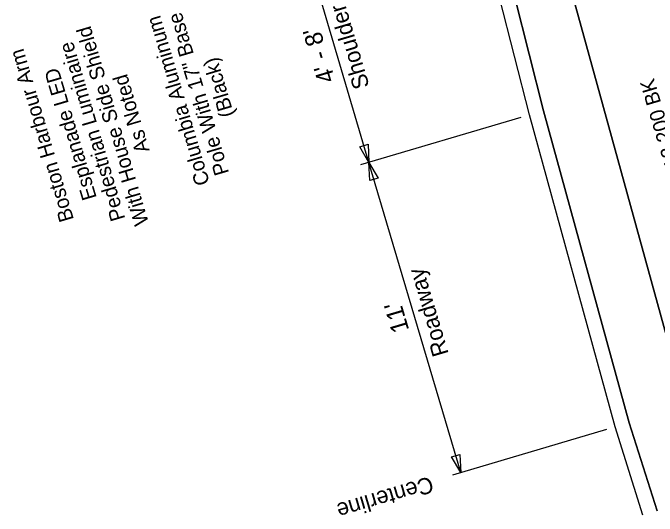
# Model space of a CAD drawing. Extents: x 1111051 to 1111820, y 617600 to 618625.
# Drawn here: x 1111518.6 to 1111693.5, y 617847.4 to 617984.1 of the extents above; entities that cross this region are included whole.
import ezdxf

# ---------------------------------------------------------------- set-up
doc = ezdxf.new("R2010")
doc.units = 0
for name, color, linetype in [('ANNOTATION', 7, 'Continuous'), ('D_Roadway_Edge_Shoulder', 7, 'Continuous'), ('D_Roadway_Edge_TW', 7, 'Continuous'), ('D_Roadway_SubGrade', 7, 'Continuous'), ('DIMENSIONS', 7, 'Continuous'), ('PATTERNING', 7, 'Continuous'), ('Prp Liting', 7, 'Continuous')]:
    doc.layers.add(name, color=color, linetype=linetype)

msp = doc.modelspace()

# ---------------------------------------------------------------- linework, layer by layer
at = {"layer": 'D_Roadway_Edge_Shoulder'}
for p, q in [((1111658.8, 617956.37), (1111643.11, 618018.35)), ((1111646.94, 618019.49), (1111662.63, 617957.5))]:
    msp.add_line(p, q, dxfattribs=at)
at = {"layer": 'D_Roadway_Edge_TW'}
for p, q in [((1111662.63, 617957.5), (1111685.88, 617872.77)), ((1111682.05, 617871.64), (1111658.8, 617956.37)), ((1111693.48, 617848.85), (1111685.88, 617872.77)), ((1111689.65, 617847.71), (1111682.05, 617871.64))]:
    msp.add_line(p, q, dxfattribs=at)
at = {"layer": 'D_Roadway_SubGrade'}
for p, q in [((1111661.03, 618023.66), (1111677.94, 617962.03)), ((1111662.63, 617957.5), (1111646.94, 618019.49)), ((1111677.94, 617962.03), (1111701.19, 617877.3)), ((1111685.88, 617872.77), (1111662.63, 617957.5)), ((1111693.48, 617848.85), (1111685.88, 617872.77))]:
    msp.add_line(p, q, dxfattribs=at)
at = {"layer": 'DIMENSIONS'}
for p, q in [((1111615.25, 617943.48), (1111597.1, 618004.77)), ((1111656.5, 617955.69), (1111612.95, 617942.8)), ((1111640.18, 617859.24), (1111615.25, 617943.48)), ((1111679.75, 617870.96), (1111637.89, 617858.56))]:
    msp.add_line(p, q, dxfattribs=at)
for points in [[(1111615.04, 617948.41), (1111615.25, 617943.48), (1111612.74, 617947.73)], [(1111615.46, 617938.54), (1111615.25, 617943.48), (1111617.76, 617939.22)], [(1111639.97, 617864.18), (1111640.18, 617859.24), (1111637.68, 617863.5)]]:
    msp.add_lwpolyline(points, close=True, dxfattribs=at)
at = {"layer": 'PATTERNING'}
for p, q in [((1111677.94, 617962.03), (1111661.03, 618023.66)), ((1111646.94, 618019.49), (1111662.63, 617957.5)), ((1111701.19, 617877.3), (1111677.94, 617962.03)), ((1111662.63, 617957.5), (1111685.88, 617872.77)), ((1111685.88, 617872.77), (1111693.48, 617848.85))]:
    msp.add_line(p, q, dxfattribs=at)

# ---------------------------------------------------------------- texts
at = {"layer": 'ANNOTATION'}
for s, rotation, p in [('Shoulder', 106.4903, (1111615.44, 617964.14)), ('Roadway', 106.4903, (1111636.93, 617891.53)), ('Centerline', 196.4903, (1111631.97, 617858.31))]:
    msp.add_text(s, height=4.425, rotation=rotation, dxfattribs=at).set_placement(p)
at = {"layer": 'Prp Liting'}
for s, height, p in [('Columbia Aluminum', 3.993, (1111572.08, 617937.86)), ('Pole With 17" Base', 3.993, (1111577.31, 617940.62)), ('With House Side Shield', 3.993, (1111555.53, 617927.01)), ("4' - 8'", 4.792, (1111606.13, 617965.84)), ('Pedestrian Luminaire', 3.993, (1111549.13, 617928.21)), ('Boston Harbour Arm', 3.993, (1111535.19, 617927.99)), ('(Black)', 3.993, (1111578.69, 617956.37)), ('Esplanade LED', 3.993, (1111541.4, 617933.89)), ('As Noted', 3.993, (1111555.74, 617946.7)), ('ESPL2 P20 40K AS S B 7 DS WLDF13 200 BK', 3.993, (1111724.43, 617858.93)), ("11'", 4.792, (1111626.21, 617898))]:
    msp.add_text(s, height=height, rotation=106.4903, dxfattribs=at).set_placement(p)

doc.saveas('drawing.dxf')
